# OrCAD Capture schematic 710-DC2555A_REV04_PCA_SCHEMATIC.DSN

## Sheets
1 PAGE2: size Custom; company: ANALOG DEVICES; note: DEMO BOARD BILL OF MATERIALS; note: SINGLE 3.6V, 1A LiFePO4 CELL WIRELESS BATTERY CHARGER
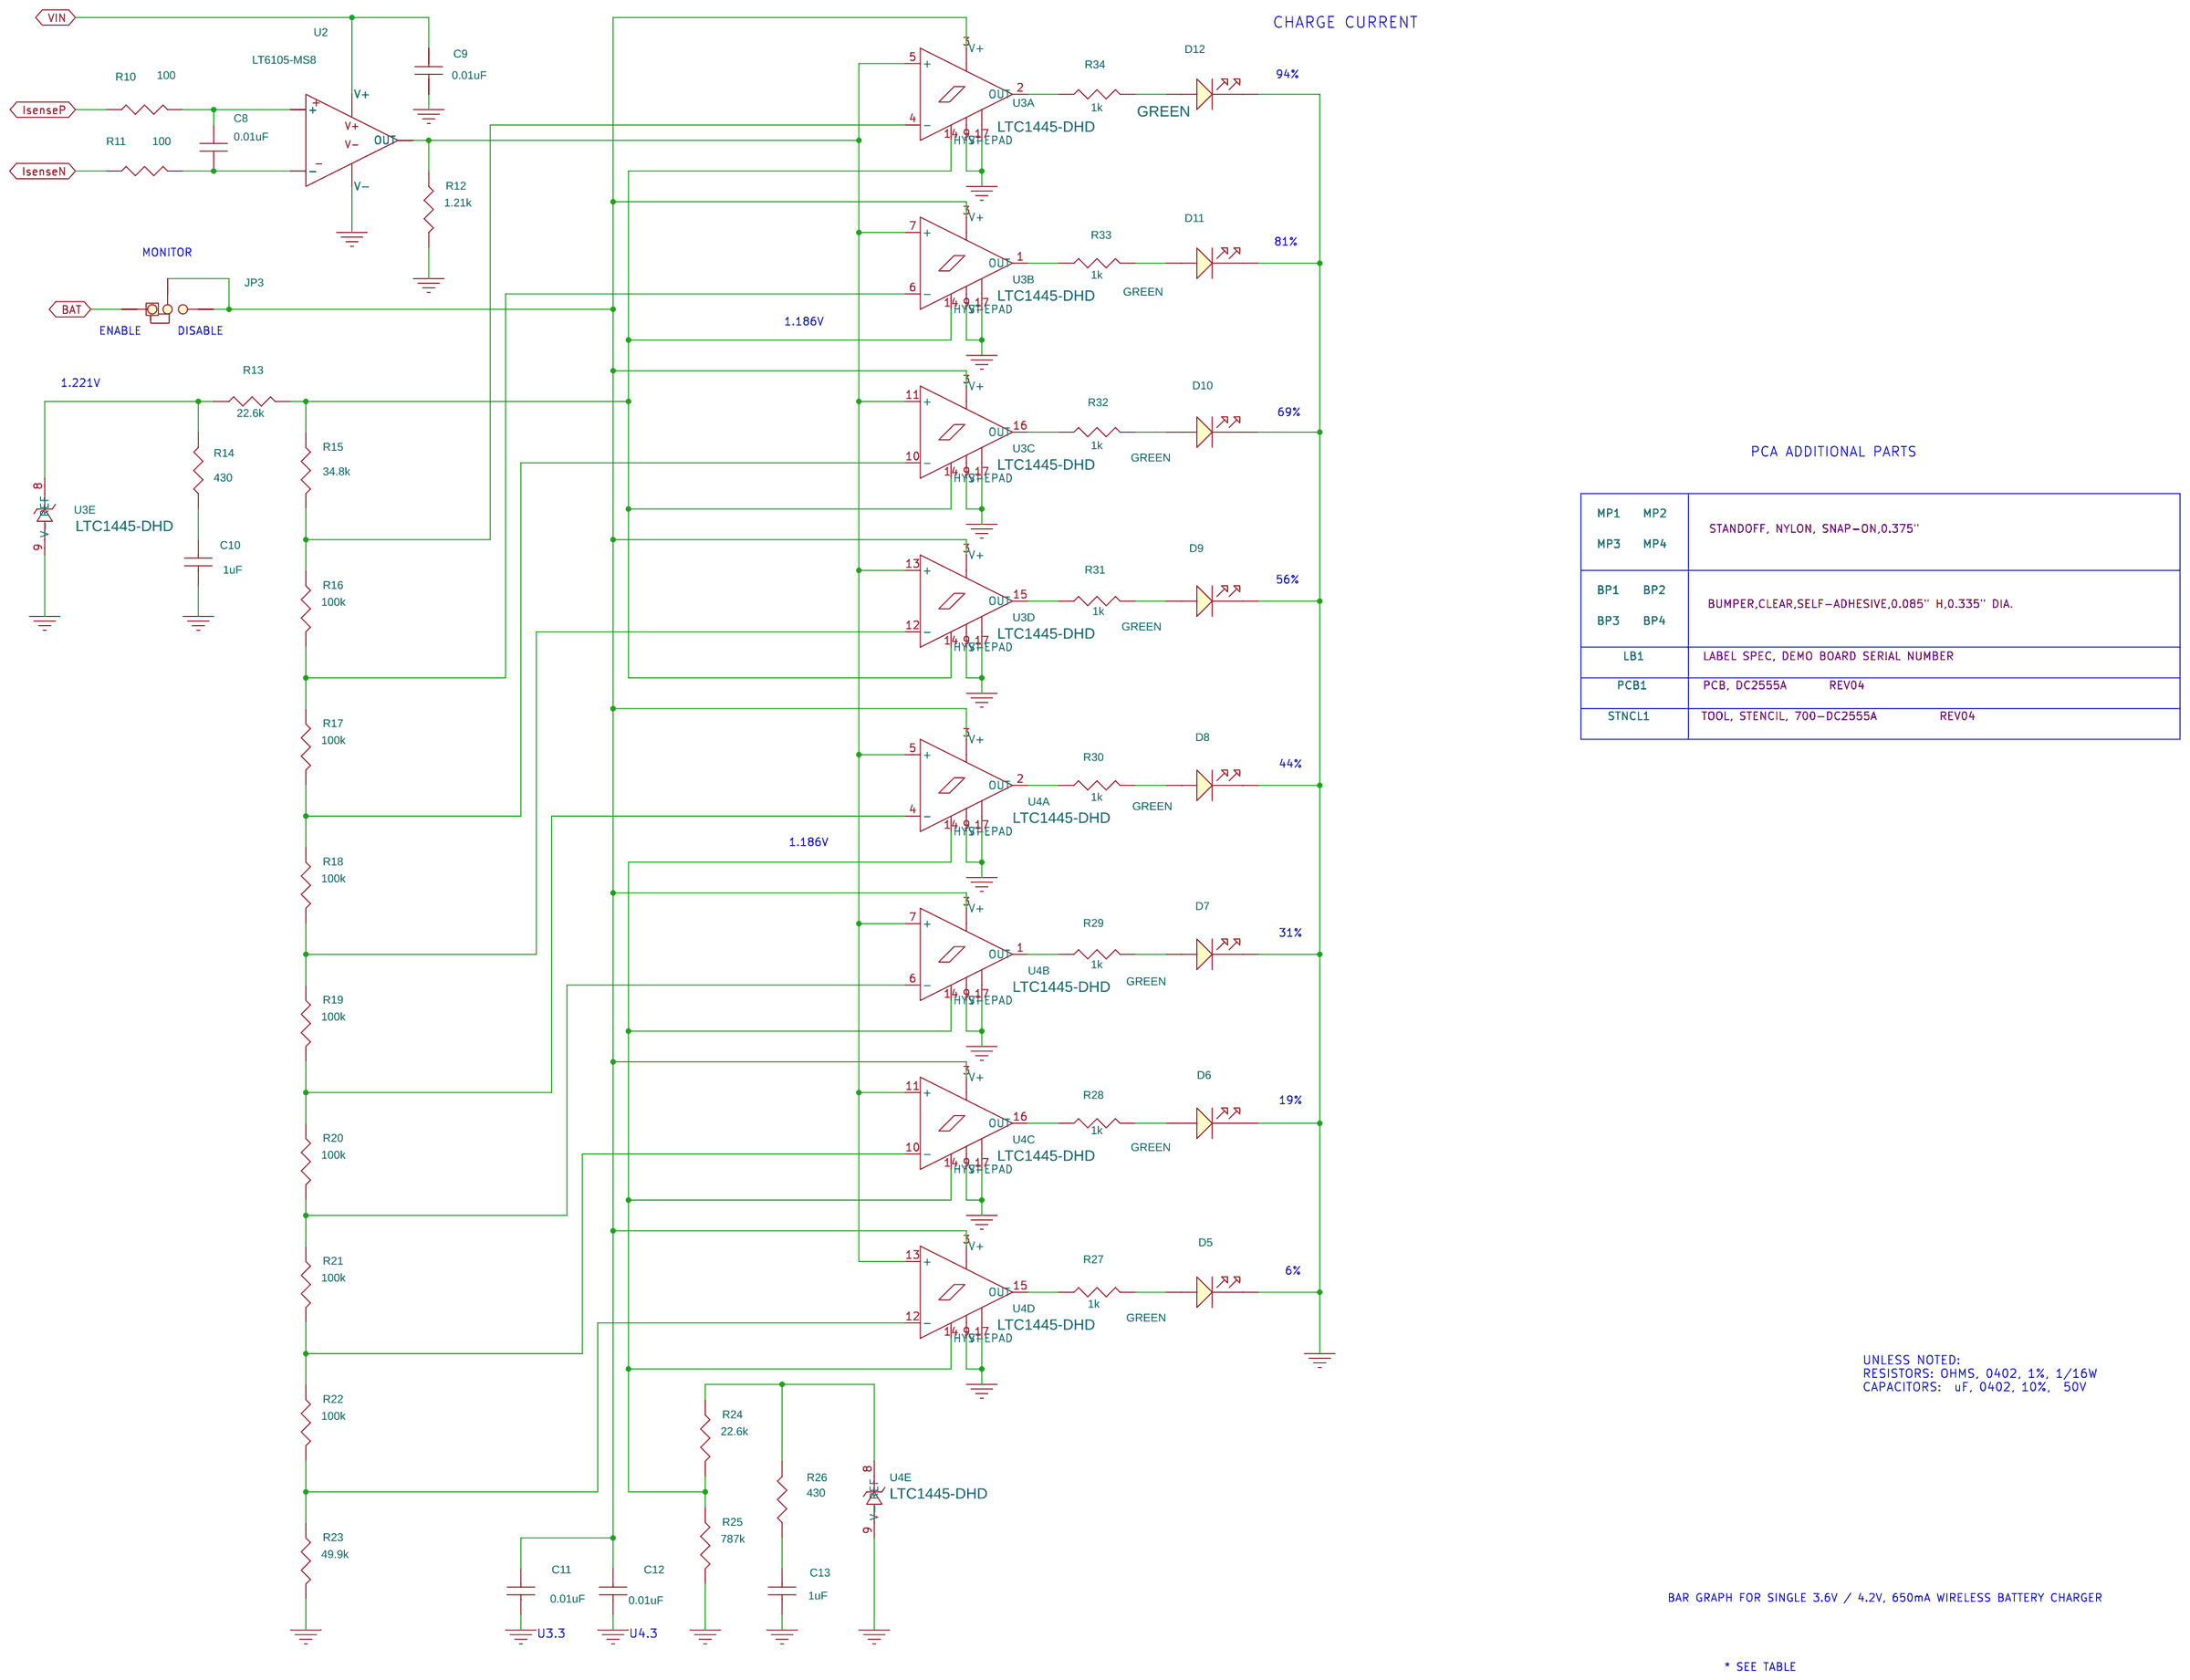
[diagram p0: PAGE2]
2 PAGE1: size Custom
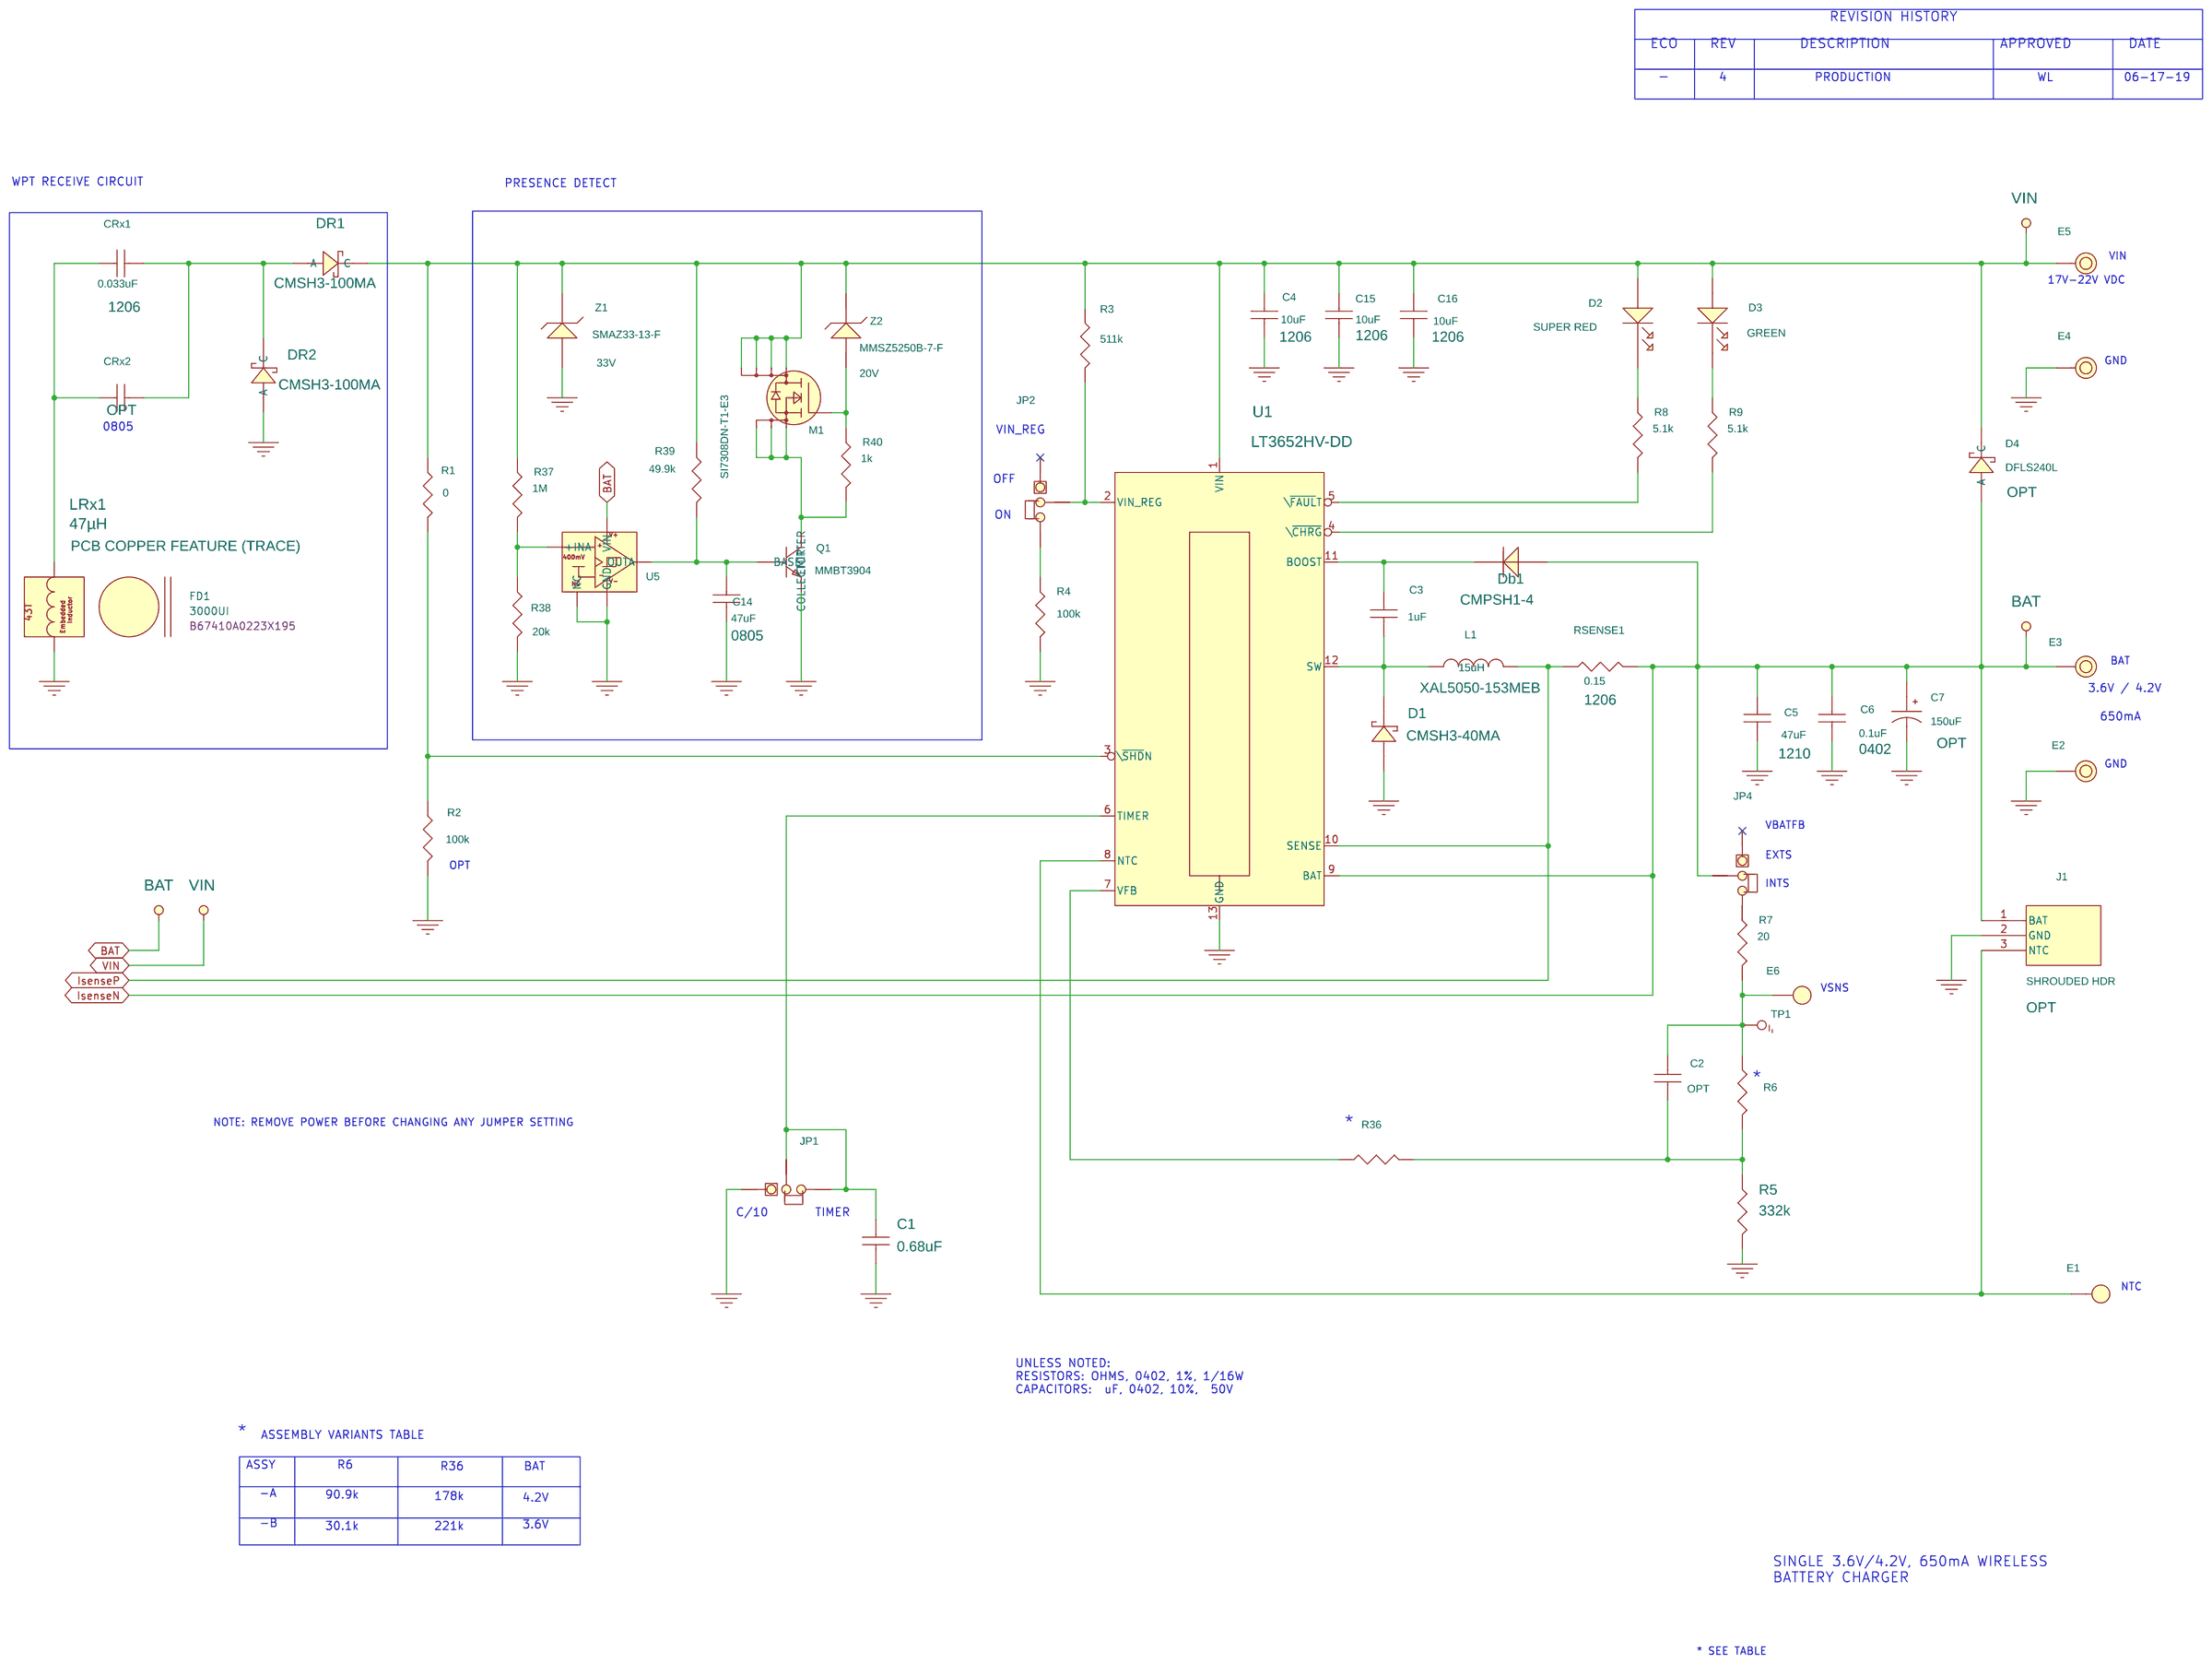
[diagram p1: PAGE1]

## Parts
sheet PAGE1
C1  0.68uF  [CC0402M]
C2  OPT  [CC0402M]
C3  1uF  [CC0402M]
C4  10uF  [CC1206N]
C5  47uF  [CC1210N]
C6  0.1uF  [CC0402M]
C7  150uF  [CAPMP7343N]
C14  47uF  [CC0805N]
C15  10uF  [CC1206N]
C16  10uF  [CC1206N]
CRx1  0.033uF  [CC1206N]
CRx2  1800pF  [CC0805N]
D1  CMSH3-40MA  [SMA-N]
D2  SUPER RED  [LED_0603]
D3  GREEN  [LED_0603]
D4  DFLS240L  [POWERDI-123]
Db1  CMPSH1-4  [SOT23F-3N]
DR1  CMSH3-100MA  [SMA-N]
DR2  CMSH3-100MA  [SMA-N]
E1  TEST POINT  [MILLMAX2308]
E2  TEST POINT  [MILLMAX2501]
E3  TEST POINT  [MILLMAX2501]
E4  TEST POINT  [MILLMAX2501]
E5  TEST POINT  [MILLMAX2501]
E6  TEST POINT  [MILLMAX2308]
FD1  3000UI  [TDK-B67410A223X195]
J1  SHROUDED HDR  [CON-HIROSE-DF3-3P-2DSA]
JP1  HDR.  [HD1X3-079]
JP2  HDR.  [HD1X3-079]
JP4  HDR.  [HD1X3-079]
L1  15uH  [COILCRAFT-XAL50]
LRx1  47µH  [EMB_COIL_43T]
M1  SI7308DN-T1-E3  [VISHAY-POWERPAK1212-8S]
Q1  MMBT3904  [SOT23-3N]
R1  0  [CR0402M]
R2  100k  [CR0402M]
R3  511k  [CR0402M]
R4  100k  [CR0402M]
R5  332k  [CR0402M]
R6  90.9k  [CR0402M]
R7  20  [CR0402M]
R8  5.1k  [CR0603N]
R9  5.1k  [CR0603N]
R36  178k  [CR0402M]
R37  1M  [CR0402M]
R38  20k  [CR0402M]
R39  49.9k  [CR0402M]
R40  1k  [CR0402M]
RSENSE1  0.15  [SUSUMU-KRL1632]
TP1  COPPER FEATURE PAD  [PADSTYLE1]
U1  LT3652HV-DD  [LTC-DD-12-1725]
U5  LT6703HV-S5-3  [LTC-S5-5-1635]
XJP3  SHUNT
XJP4  SHUNT
XJP6  SHUNT
Z1  SMAZ33-13-F  [SMA-N]
Z2  MMSZ5250B-7-F  [SOD-123N]
sheet PAGE2
BP1  BUMPER  [UNASSIGNED]
BP2  BUMPER  [UNASSIGNED]
BP3  BUMPER  [UNASSIGNED]
BP4  BUMPER  [UNASSIGNED]
C8  0.01uF  [CC0402M]
C9  0.01uF  [CC0402M]
C10  1uF  [CC0402M]
C11  0.01uF  [CC0402M]
C12  0.01uF  [CC0402M]
C13  1uF  [CC0402M]
D5  GREEN  [LED_0603]
D6  GREEN  [LED_0603]
D7  GREEN  [LED_0603]
D8  GREEN  [LED_0603]
D9  GREEN  [LED_0603]
D10  GREEN  [LED_0603]
D11  GREEN  [LED_0603]
D12  GREEN  [LED_0603]
JP3  HDR.  [HD1X3-079]
LB1  LABEL  [895-0154_REV01]
MP1  STANDOFF, NYLON, SNAP-ON  [KEYSTONE_8829-8834]
MP2  STANDOFF, NYLON, SNAP-ON  [KEYSTONE_8829-8834]
MP3  STANDOFF, NYLON, SNAP-ON  [KEYSTONE_8829-8834]
MP4  STANDOFF, NYLON, SNAP-ON  [KEYSTONE_8829-8834]
PCB1  PCB, DC2555A
R10  100  [CR0402M]
R11  100  [CR0402M]
R12  1.21k  [CR0402M]
R13  22.6k  [CR0402M]
R14  430  [CR0402M]
R15  34.8k  [CR0402M]
R16  100k  [CR0402M]
R17  100k  [CR0402M]
R18  100k  [CR0402M]
R19  100k  [CR0402M]
R20  100k  [CR0402M]
R21  100k  [CR0402M]
R22  100k  [CR0402M]
R23  49.9k  [CR0402M]
R24  22.6k  [CR0402M]
R25  787k  [CR0402M]
R26  430  [CR0402M]
R27  1k  [CR0402M]
R28  1k  [CR0402M]
R29  1k  [CR0402M]
R30  1k  [CR0402M]
R31  1k  [CR0402M]
R32  1k  [CR0402M]
R33  1k  [CR0402M]
R34  1k  [CR0402M]
STNCL1  TOOL, STENCIL, 700-DC2555A
U2  LT6105-MS8  [LTC-MS8-8-1660]
U3  LTC1445-DHD  [LTC-DHD-16-1707]  (sections A,B,C,D,E)
U4  LTC1445-DHD  [LTC-DHD-16-1707]  (sections A,B,C,D,E)
XJP5  SHUNT

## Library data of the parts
C1 = CAP: CAP.,0.68uF,X5R,10V,10%,0402; CLASS: DISCRETE; Dielectric Type: X5R; FPLIST: CC0402N,CC0402L,CC0402M; Inventory Qty: 12568; Manufacturer: MURATA; Manufacturer PN: GRM155R61A684KE15D; PART_NUMBER: 150-3555; Package Size: 0402; Rated Voltage: 10V; Tolerance: 10%
C2 = CAP: CAP., OPTION, 0402; BOM Notes: NO STUFF; CLASS: DISCRETE; PART_NUMBER: 150-3148; Package Size: 0402; Package Type: SMD
C3 C10 C13 = CAP: CAP.,1uF,X5R,16V,10%,0402; CLASS: DISCRETE; Dielectric Type: X5R; FPLIST: CC0402N,CC0402L,CC0402M; Inventory Qty: 40680; Manufacturer: AVX; Manufacturer PN: 0402YD105KAT2A; PART_NUMBER: 150-0250; Package Size: 0402; Rated Voltage: 16V; Tolerance: 10%
C4 C15 C16 = CAP: CAP.,10uF,X5R,50V,10%,1206; CLASS: DISCRETE; Dielectric Type: X5R; FPLIST: CC1206N,CC1206L,CC1206M; Inventory Qty: 21192; Manufacturer: MURATA; Manufacturer PN: GRM31CR61H106KA12L; PART_NUMBER: 150-0330; Package Size: 1206; Rated Voltage: 50V; Tolerance: 10%
C5 = CAP: CAP.,47uF,X5R,16V,20%,1210; CLASS: DISCRETE; Dielectric Type: X5R; FPLIST: CC1210N,CC1210L,CC1210M; Inventory Qty: 3788; Manufacturer: AVX; Manufacturer PN: 1210YD476MAT2A; PART_NUMBER: 150-3254; Package Size: 1210; Rated Voltage: 16V; Tolerance: 20%
C6 = CAP: CAP.,0.1uF,X5R,50V,10%,0402; CLASS: DISCRETE; Dielectric Type: X5R; FPLIST: CC0402N,CC0402L,CC0402M; Inventory Qty: 1680; Manufacturer: AVX; Manufacturer PN: 04025D104KAT2A; PART_NUMBER: 150-3561; Package Size: 0402; Package Type: Surface Mount, MLCC; Rated Voltage: 50V; Temperature Coefficient: X5R; Tolerance: 10%
C7 = CAP_P_ALT: CAP.,150uF,TANT. POSCAP,10V,20%,7343,D3L; BOM Notes: NO STUFF; CLASS: DISCRETE; Dielectric Type: TANT. POSCAP; FPLIST: CAPMP7343N,CAPMP7343L,CAPMP7343N; Inventory Qty: 0; Manufacturer: PANASONIC; Manufacturer PN: 10TPF150ML; PART_FIELD_01: OPT; PART_NUMBER: 150-2018; Package Size: 7343,D3L; Rated Voltage: 10V; Tolerance: 20%
C14 = CAP: CAP.,47uF,X5R,6.3V,20%,0805; CLASS: DISCRETE; Dielectric Type: X5R; FPLIST: CC0805N,CC0805L,CC0805M; Inventory Qty: 29694; Manufacturer: MURATA; Manufacturer PN: GRM21BR60J476ME15L; PART_NUMBER: 150-0140; Package Size: 0805; Rated Voltage: 6.3V; Tolerance: 20%
CRx1 = CAP: CAP.,0.033uF,NP0,100V,5%,1206; CLASS: DISCRETE; Dielectric Type: NP0; FPLIST: CC1206N,CC1206L,CC1206M; Inventory Qty: 2722; Manufacturer: TDK; Manufacturer PN: C3216NP02A333J160AA; PART_NUMBER: 150-3562; Package Size: 1206; Package Type: Surface Mount, MLCC; Rated Voltage: 100V; Temperature Coefficient: C0G, NP0; Tolerance: 5%
CRx2 = CAP: CAP CER 1800PF 100V C0G 0805; BOM Notes: NO STUFF; CLASS: DISCRETE; Dielectric Type: Capacitors; Manufacturer: TDK Corporation; Manufacturer PN: C2012C0G2A182J085AA; PART_FIELD_01: OPT; PART_NUMBER: TMP-2658; Package Size: 0805 (2012 Metric); Package Type: Surface Mount, MLCC; Rated Voltage: 100V; Temperature Coefficient: C0G, NP0; Tolerance: 5%
D1 = DIODE_SCHOTTKY_A_ALT: DIODE,SCHOTTKY RECT.,40V,3A,SMA; CLASS: DISCRETE; FPLIST: SMA-N,SMA-L,SMA-M; Inventory Qty: 920; Manufacturer: CENTRAL SEMI.; Manufacturer PN: CMSH3-40MA TR13 LEAD FREE; Max Forward Current or Rated Power: 3A; PART_NUMBER: 210-0191; Package Size: DO-214AC, SMA; Package Type: SMA; Rated Voltage: 40V; Rated Voltage or Zener Voltage: 40V
D2 = LED_ALT: LED,SUPER RED,MILKY WHITE DIFF.,0603; CLASS: DISCRETE; Inventory Qty: 8820; Manufacturer: LUMEX; Manufacturer PN: SML-LX0603SRW-TR; PART_NUMBER: 270-0084; Package Size: 0603 (1608 Metric); Package Type: 0603
D3 D5-D12 = LED_ALT: LED,GREEN,MILKY WHITE DIFFUSED,0603; CLASS: DISCRETE; Inventory Qty: 9994; Manufacturer: LUMEX; Manufacturer PN: SML-LX0603SUGW-TR; PART_NUMBER: 270-0091; Package Size: 0603 (1608 Metric); Package Type: 0603
D4 = DIODE_SCHOTTKY_A: DIODE,SCHOTTKY,40V,2A,PowerDI123-2,AEC-Q101; BOM NOTES: NO STUFF; CLASS: DISCRETE; Inventory Qty: 4023; Manufacturer: DIODES INC.; Manufacturer PN: DFLS240L-7; Max Forward Current or Rated Power: 2A; PART_FIELD_01: OPT; PART_NUMBER: 210-0158; Package Type: PowerDI123-2; Rated Voltage: 40V; Rated Voltage or Zener Voltage: 40V
Db1 = DIODE_SOT_1: DIODE,SCHOTTKY RECT.,40V,1.75A,SOT-23F; CLASS: DISCRETE; FPLIST: SOT23-3N,SOT23-3L,SOT23-3M; Inventory Qty: 780; Manufacturer: CENTRAL SEMI.; Manufacturer PN: CMPSH1-4 TR LEAD FREE; Max Forward Current or Rated Power: 1.75A; PART_NUMBER: 210-0193; Package Size: SOT-23-3 Flat Leads; Package Type: SOT-23F; Rated Voltage: 40V; Rated Voltage or Zener Voltage: 40V
DR1 DR2 = DIODE_SCHOTTKY_A: DIODE,SCHOTTKY,100V,3A,SMA; CLASS: DISCRETE; FPLIST: SMA-N,SMA-L,SMA-M; Inventory Qty: 800; Manufacturer: CENTRAL SEMI.; Manufacturer PN: CMSH3-100MA TR13 PBFREE; Max Forward Current or Rated Power: 3A; PART_NUMBER: 210-0275; Package Size: DO-214AC, SMA; Package Type: SMA; Rated Voltage: 100V; Rated Voltage or Zener Voltage: 100V
E1 E6 = TEST_POINT_.156_MILL-MAX_2308: TEST POINT,TURRET,0.064" MTG. HOLE,PCB 0.062" THICK; CLASS: IO; FPLIST: MILLMAX2308,MILLMAX2308-2; Inventory Qty: 804832; Manufacturer: MILL-MAX; Manufacturer PN: 2308-2-00-80-00-00-07-0; PART_NUMBER: 260-0004
E2-E5 = TESTPOINT_.219_MILL-MAX_2501: TEST POINT,TURRET,0.094" MTG. HOLE,PCB 0.062" THICK; CLASS: IO; Inventory Qty: 509910; Manufacturer: MILL-MAX; Manufacturer PN: 2501-2-00-80-00-00-07-0; PART_NUMBER: 260-0003
FD1 = IND-FERRITE_DISK: IND.,3000ui,FERRITE DISK,+/-25%,ROD25.5/0.6; CLASS: DISCRETE; Inventory Qty: 1824; Manufacturer: TDK; Manufacturer PN: B67410A0223X195; PART_NUMBER: 200-0522; Tolerance: +/-25%
J1 = CON-HIROSE-DF3-3P-2DSA: CONN.,SHROUDED HDR,MALE,1x3,2mm,STR, THT,AU; BOM Notes: NO STUFF; CLASS: IO; Inventory Qty: 0; Manufacturer: HIROSE ELECTRIC; Manufacturer PN: DF3-3P-2DSA(01); Operating Temperature Minimum: -55C - 105C; PART_FIELD_01: OPT; PART_NUMBER: 250-0713
JP1-JP4 = 1X3_C: CONN.,HDR.,MALE,1x3,2mm,THT, STR,NO SUBS. ALLOWED; CLASS: IO; Inventory Qty: 9734; Manufacturer: SAMTEC; Manufacturer PN: TMM-103-02-L-S; PART_NUMBER: 250-0638
L1 = IND: IND.,15uH,PWR,20%,3.9A,76.70mOhms,5.48x5.28mm,AEC-Q200; CLASS: DISCRETE; Inventory Qty: 0; Manufacturer: COILCRAFT; Manufacturer PN: XAL5050-153MEB; PART_NUMBER: 200-0514; Package Size: 5.48x5.28mm; Tolerance: 20%
LRx1 = LPS4018-153MLC_1: PART_FIELD_01: PCB COPPER FEATURE (TRACE)
M1 = MOSFET_N-CH_G: XSTR.,MOSFET,N-CH,60V,6A,PowerPAK 1212-8; CLASS: DISCRETE; Inventory Qty: 2624; Manufacturer: VISHAY; Manufacturer PN: Si7308DN-T1-GE3; PART_NUMBER: 240-0291; Package Size: PowerPAK® 1212-8; Package Type: PowerPAK 1212-8; Polarity: N-Channel; Rated Voltage: 60V
Q1 = MMBT3904_SOT-23: XSTR.,NPN,40V,200mA,SOT23-3; CLASS: DISCRETE; FPLIST: SOT23-3N,SOT23-3L,SOT23-3M; Inventory Qty: 14639; Manufacturer: FAIRCHILD SEMI; PART_NUMBER: 240-0014; Package Type: SOT23-3; Rated Voltage: 40V
R1 = RES: RES.,0 OHM,1/16W,0402; CLASS: DISCRETE; FPLIST: CR0402N,CR0402L,CR0402M; Inventory Qty: 222931; Manufacturer: ROHM; Manufacturer PN: MCR01MZPJ000; PART_NUMBER: 100-0215; Package Size: 0402; Rated Power: 1/16W
R2 = RES: RES.,100k OHMS,1%,1/16W,0402,AEC-Q200; CLASS: DISCRETE; FPLIST: CR0402N,CR0402L,CR0402M; Inventory Qty: 136632; Manufacturer: VISHAY; Manufacturer PN: CRCW0402100KFKED; PART_NUMBER: 100-2396; Package Size: 0402; Rated Power: 1/16W; Temperature Coefficient: 100ppm; Tolerance: 1%
R3 = RES: RES.,511k OHMS,1%,1/16W,0402,AEC-Q200; CLASS: DISCRETE; FPLIST: CR0402N,CR0402L,CR0402M; Inventory Qty: 20028; Manufacturer: NIC; Manufacturer PN: NRC04F5113TRF; PART_NUMBER: 100-0583; Package Size: 0402; Rated Power: 1/16W; Temperature Coefficient: +/-100PPM; Tolerance: 1%
R4 = RES: RES.,100k OHMS,1%,1/10W,0402,AEC-Q200; CLASS: DISCRETE; FPLIST: CR0402N,CR0402L,CR0402M; Inventory Qty: 127964; Manufacturer: KOA SPEER; Manufacturer PN: RK73H1ETTP1003F; PART_NUMBER: 100-2407; Package Size: 0402; Rated Power: 1/10W; Temperature Coefficient: 100ppm/C; Tolerance: 1%
R5 = RES: RES.,332k OHMS,1%,1/16W,0402,AEC-Q200; CLASS: DISCRETE; FPLIST: CR0402N,CR0402L,CR0402M; Inventory Qty: 16850; Manufacturer: NIC; Manufacturer PN: NRC04F3323TRF; PART_NUMBER: 100-2664; Package Size: 0402; Rated Power: 1/16W; Temperature Coefficient: 100ppm/C; Tolerance: 1%
R6 = RES: RES.,90.9k OHMS,1%,1/16W,0402,AEC-Q200; CLASS: DISCRETE; FPLIST: CR0402N,CR0402L,CR0402M; Inventory Qty: 69042; Manufacturer: NIC; Manufacturer PN: NRC04F9092TRF; PART_NUMBER: 100-2879; Package Size: 0402; Rated Power: 1/16W; Temperature Coefficient: 100ppm; Tolerance: 1%
R7 = RES: RES.,20 OHMS,5%,1/16W,0402; CLASS: DISCRETE; FPLIST: CR0402N,CR0402L,CR0402M; Inventory Qty: 14501; Manufacturer: KOA SPEER; Manufacturer PN: RK73B1ETTP200J; PART_NUMBER: 100-2384; Package Size: 0402; Rated Power: 1/16W; Temperature Coefficient: 200ppm/C; Tolerance: 5%
R8 R9 = RES: RES.,5.1k OHMS,5%,1/10W,0603,AEC-Q200; CLASS: DISCRETE; FPLIST: CR0603N,CR0603L,CR0603M; Inventory Qty: 35732; Manufacturer: NIC; Manufacturer PN: NRC06J512TRF; PART_NUMBER: 100-0463; Package Size: 0603; Rated Power: 1/10W; Temperature Coefficient: 200ppm; Tolerance: 5%
R36 = RES: RES.,178K OHMS,1%,1/16W,0402,AEC-Q200; CLASS: DISCRETE; FPLIST: CR0402N,CR0402L,CR0402M; Inventory Qty: 5000; Manufacturer: NIC; Manufacturer PN: NRC04F1783TRF; PART_NUMBER: 100-0976; Package Size: 0402; Rated Power: 1/16W; Temperature Coefficient: +/-100PPM; Tolerance: 1%
R37 = RES: RES.,1M OHMS,1%,1/16W,0402,AEC-Q200; CLASS: DISCRETE; FPLIST: CR0402N,CR0402L,CR0402M; Inventory Qty: 93609; Manufacturer: STACKPOLE ELECTRONICS, INC.; Manufacturer PN: RMCF0402FT1M00; PART_NUMBER: 100-2457; Package Size: 0402; Rated Power: 1/16W; Temperature Coefficient: 100ppm; Tolerance: 1%
R38 = RES: RES.,20k OHMS,1%,1/16W,0402,AEC-Q200; CLASS: DISCRETE; FPLIST: CR0402N,CR0402L,CR0402M; Inventory Qty: 11200; Manufacturer: NIC; Manufacturer PN: NRC04F2002TRF; PART_NUMBER: 100-2549; Package Size: 0402; Rated Power: 1/16W; Temperature Coefficient: 100ppm/C; Tolerance: 1%
R23 R39 = RES: RES.,49.9k OHMS,1%,1/16W,0402,AEC-Q200; CLASS: DISCRETE; FPLIST: CR0402N,CR0402L,CR0402M; Inventory Qty: 40010; Manufacturer: NIC; Manufacturer PN: NRC04F4992TRF; PART_NUMBER: 100-2406; Package Size: 0402; Rated Power: 1/16W; Temperature Coefficient: 100ppm/C; Tolerance: 1%
R40 = RES: RES.,1k OHM,1%,1/16W,0402,AEC-Q200; CLASS: DISCRETE; FPLIST: CR0402N,CR0402L,CR0402M; Inventory Qty: 114186; Manufacturer: VISHAY; Manufacturer PN: CRCW04021K00FKED; PART_NUMBER: 100-2456; Package Size: 0402; Rated Power: 1/16W; Temperature Coefficient: 100ppm/C; Tolerance: 1%
RSENSE1 = RES: RES.,0.15 OHM,1%,3/4W,1206,SHORT-SIDE TERM.,AEC-Q200,METAL,SENSE; CLASS: DISCRETE; Inventory Qty: 0; Manufacturer: Susumu; Manufacturer PN: KRL1632E-M-R150-F-T5; PART_NUMBER: 100-1454; Package Size: 1206; Rated Power: 3/4W; Temperature Coefficient: +/-50ppm; Tolerance: 1%
TP1 = PAD_SMALL_FILLED: TESTPOINT, PCB COPPER FEATURE; CLASS: IO; Manufacturer: N/A; Manufacturer PN: N/A; PART_NUMBER: PCBPADS-11
U1 = LT3652HV-DD: IC,PWR Tracking 2A Batt.Charger,3x3 DFN-12; CLASS: IC; Inventory Qty: 0; Manufacturer: LINEAR TECH.; Manufacturer PN: LT3652HVEDD#PBF; PART_NUMBER: LT3652HVEDD#PBF; Package Type: 3x3 DFN-12
U5 = LT6703HV-3-S5: IC,uPower, Comparator w/400mV Ref,SOT23-5; CLASS: IC; Inventory Qty: 0; Manufacturer: LINEAR TECH.; Manufacturer PN: LT6703HVIS5-3#PBF; PART_NUMBER: LT6703HVIS5-3#PBF; Package Size: TSOT-23; Package Type: SOT23-5
XJP3-XJP6 = SHUNT_2MM_B: CONN.,SHUNT,FEMALE,2 POS,2mm; CLASS: IO; Inventory Qty: 63006; Manufacturer: Wurth Elektronik; Manufacturer PN: 60800213421; PART_NUMBER: 250-0485
Z1 = ZENER_ALT: DIODE,ZENER,33V,1W,SMA; CLASS: DISCRETE; Inventory Qty: 0; Manufacturer: DIODES INC.; PART_NUMBER: 210-0443; Package Size: DO-214AC, SMA; Package Type: SMA; Rated Voltage or Zener Voltage: 33V
Z2 = ZENER_ALT: DIODE,ZENER,20V,500mW,SOD-123; CLASS: DISCRETE; Inventory Qty: 0; Manufacturer: DIODES INC.; PART_NUMBER: 210-0444; Package Size: SOD-123; Package Type: SOD-123; Rated Power: 500mW; Rated Voltage or Zener Voltage: 20V
BP1-BP4 = BLANK_MECHANICAL_PART: BUMPER,CLEAR,SELF-ADHESIVE,0.085" H,0.335" DIA.; CLASS: DISCRETE; Inventory Qty: 6096; Manufacturer: KEYSTONE; Manufacturer PN: 784-C; PART_NUMBER: 763-0027
C8 C9 C11 C12 = CAP: CAP.,0.01uF,X7R,50V,10%,0402; CLASS: DISCRETE; Dielectric Type: X7R; FPLIST: CC0402N,CC0402L,CC0402M; Inventory Qty: 65996; Manufacturer: KEMET; Manufacturer PN: C0402C103K5RAC7867; PART_NUMBER: 150-0041; Package Size: 0402; Rated Voltage: 50V; Tolerance: 10%
LB1 = BLANK_LABEL: LABEL SPEC, DEMO BOARD SERIAL NUMBER; Inventory Qty: 0; Manufacturer: BRADY; Manufacturer PN: THT-96-717-10; PART_NUMBER: 895-0154
MP1-MP4 = BLANK_PINLESS_MECHANICAL_PART: STANDOFF, NYLON, SNAP-ON,0.375"; CLASS: DISCRETE; Inventory Qty: 158796; Manufacturer: KEYSTONE; Manufacturer PN: 8832; PART_NUMBER: 763-0008
PCB1 = BLANK_PCB_PART: BOM Notes: REV04; CLASS: DISCRETE; Inventory Qty: 0; Manufacturer: PHASE 3; Manufacturer PN: 600-DC2555A; PART_NUMBER: 600-DC2555A
R10 R11 = RES: RES.,100 OHMS,1%,1/16W,0402,AEC-Q200; CLASS: DISCRETE; FPLIST: CR0402N,CR0402L,CR0402M; Inventory Qty: 91341; Manufacturer: KOA SPEER; Manufacturer PN: RK73H1ETTP1000F; PART_NUMBER: 100-0175; Package Size: 0402; Rated Power: 1/16W; Temperature Coefficient: 100ppm/C; Tolerance: 1%
R12 = RES: RES.,1.21k OHMS,1%,1/16W,0402,AEC-Q200; CLASS: DISCRETE; FPLIST: CR0402N,CR0402L,CR0402M; Inventory Qty: 20000; Manufacturer: KOA SPEER; Manufacturer PN: RK73H1ETTP1211F; PART_NUMBER: 100-0011; Package Size: 0402; Rated Power: 1/16W; Temperature Coefficient: 100ppm/C; Tolerance: 1%
R13 R24 = RES: RES.,22.6k OHMS,1%,1/16W,0402,AEC-Q200; CLASS: DISCRETE; FPLIST: CR0402N,CR0402L,CR0402M; Inventory Qty: 78048; Manufacturer: NIC; Manufacturer PN: NRC04F2262TRF; PART_NUMBER: 100-2975; Package Size: 0402; Rated Power: 1/16W; Temperature Coefficient: 100; Tolerance: 1%
R14 R26 = RES: RES.,430 OHMS,5%,1/16W,0402; CLASS: DISCRETE; FPLIST: CR0402N,CR0402L,CR0402M; Inventory Qty: 39842; Manufacturer: SAMSUNG; Manufacturer PN: RC1005J431CS; PART_NUMBER: 100-0472; Package Size: 0402; Rated Power: 1/16W; Temperature Coefficient: +/-100PPM; Tolerance: 5%
R15 = RES: RES.,34.8k OHMS,1%,1/10W,0402,AEC-Q200; CLASS: DISCRETE; FPLIST: CR0402N,CR0402L,CR0402M; Inventory Qty: 5900; Manufacturer: KOA SPEER; Manufacturer PN: RK73H1ETTP3482F; PART_NUMBER: 100-0734; Package Size: 0402; Rated Power: 1/10W; Temperature Coefficient: 100ppm; Tolerance: 1%
R16-R22 = RES: RES.,100k OHMS,5%,1/16W,0402,AEC-Q200; CLASS: DISCRETE; FPLIST: CR0402N,CR0402L,CR0402M; Inventory Qty: 49572; Manufacturer: NIC; Manufacturer PN: NRC04J104TRF; PART_NUMBER: 100-0359; Package Size: 0402; Rated Power: 1/16W; Temperature Coefficient: 200ppm/C; Tolerance: 5%
R25 = RES: RES.,787k OHMS,1%,1/16W,0402,AEC-Q200; CLASS: DISCRETE; FPLIST: CR0402N,CR0402L,CR0402M; Inventory Qty: 33778; Manufacturer: NIC; Manufacturer PN: NRC04F7873TRF; PART_NUMBER: 100-0326; Package Size: 0402; Rated Power: 1/16W; Temperature Coefficient: 100ppm/C; Tolerance: 1%
R27-R34 = RES: RES.,1k OHM,5%,1/16W,0402,AEC-Q200; CLASS: DISCRETE; FPLIST: CR0402N,CR0402L,CR0402M; Inventory Qty: 83731; Manufacturer: NIC; Manufacturer PN: NRC04J102TRF; PART_NUMBER: 100-2397; Package Size: 0402; Rated Power: 1/16W; Temperature Coefficient: 200ppm; Tolerance: 5%
STNCL1 = BLANK_STENCIL_PART: BOM Notes: REV04; CLASS: DISCRETE; Inventory Qty: 0; Manufacturer: LINEAR TECH.; Manufacturer PN: 830-DC2555A; PART_NUMBER: 830-DC2555A
U2 = LT6105-MS8: IC,CURRENT SENSE AMP,MSOP-8; CLASS: IC; Inventory Qty: 20; Manufacturer: LINEAR TECH.; Manufacturer PN: LT6105CMS8#PBF; PART_NUMBER: LT6105CMS8#PBF; Package Size: 8-TSSOP, 8-MSOP (0.118", 3.00mm Width); Package Type: MSOP-8; Supply Voltage: 2.85 V - 36 V, 1.425 V - 18 V
U3 U4 = LTC1443_44_45-DHD: IC,QUAD COMPARATOR LP 1.221VREF,DFN-16 (5x4); CLASS: IC; Inventory Qty: 36; Manufacturer: LINEAR TECH.; Manufacturer PN: LTC1445CDHD#PBF; PART_NUMBER: LTC1445CDHD#PBF; Package Size: 16-WFDFN Exposed Pad; Package Type: DFN-16 (5x4); Supply Voltage: 2V-11V, 1 V-5.5V

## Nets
GND: C1.2 C4.2 C5.2 C6.2 C7.2 C9.2 C10.2 C11.2 C12.2 C13.2 C14.2 C15.2 C16.2 D1.2(A) D5.1(CATHODE) D6.1(CATHODE) D7.1(CATHODE) D8.1(CATHODE) D9.1(CATHODE) D10.1(CATHODE) D11.1(CATHODE) D12.1(CATHODE) DR2.2(A) E2.1 E4.1 J1.2(GND) JP1.1 LRx1.2 Q1.2(EMITTER) R2.2 R4.2 R5.2 R12.2 R23.2 R25.2 R38.2 U1.13(GND) U2.4(V-) U3.9(V-) U3.17(EPAD) U4.9(V-) U4.17(EPAD) U5.2(GND) U5.5(NC) Z1.2(A)
VIN: C4.1 C9.1 C15.1 C16.1 D2.2(ANODE) D3.2(ANODE) D4.1(C) DR1.1(C) E5.1 M1.5(D) M1.6(Dtab) M1.7(Dtab1) M1.8(Dtab2) R1.1 R3.1 R37.1 R39.1 U1.1(VIN) U2.2(V+) Z1.1(C) Z2.1(C)
BAT: C5.1 C6.1 C7.1 D4.2(A) Db1.1 E3.1 J1.1(BAT) JP3.1 JP4.2 R11.1 RSENSE1.2 U1.9(BAT) U5.4(VIN)
IsenseP: L1.2 R10.1 RSENSE1.1 U1.10(SENSE)
N16829716: C1.1 JP1.2 JP1.3 U1.6(TIMER)
N16838606: D3.1(CATHODE) R9.1
N16838659: D2.1(CATHODE) R8.1
N16850982: C3.2 D1.1(C) L1.1 U1.12(SW)
N16856824: E1.1(A) J1.3(NTC) U1.8(NTC)
N16882466: JP2.2 R3.2 U1.2(VIN_REG)
N16888719: C2.2 E6.1(A) R6.1 R7.2 TP1.1
N16892306: C2.1 R5.1 R6.2 R36.2
N16905248: R36.1 U1.7(VFB)
N16907155: C3.1 Db1.3 U1.11(BOOST)
N16908328: R8.2 U1.5(\~{FAUL}T)
N16908845: R9.2 U1.4(\~{CHRG})
N16910697: M1.1(S) M1.2(Stab) M1.3(Stab1) Q1.3(COLLECTOR) R40.2
N16910770: CRx1.2 CRx2.2 DR1.2(A) DR2.1(C)
N16915821: CRx1.1 CRx2.1 LRx1.1
N16935027: R13.1 R14.2 U3.8(REF)
N16935034: R13.2 R15.1 U3.14(HYST)
N16935145: C11.1 C12.1 JP3.2 JP3.3 U3.3(V+) U4.3(V+)
N16935939: R12.1 U2.5(OUT) U3.5(+) U3.7(+) U3.11(+) U3.13(+) U4.5(+) U4.7(+) U4.11(+) U4.13(+)
N16936864: C8.2 R11.2 U2.1(-)
N16936867: C8.1 R10.2 U2.8(+)
N16981836: C13.1 R26.1
N16983719: D9.2(ANODE) R31.2
N17012090: JP2.3 R4.1
N17050170: R1.2 R2.1 U1.3(\~{SHD}N)
N17067404: R24.2 R25.1 U4.14(HYST)
N17104684: R37.2 R38.1 U5.3(+INA)
N17105039: C14.1 Q1.1(BASE) R39.2 U5.1(OUTA)
N17107129: M1.4(G) R40.1 Z2.2(A)
N17109108: JP4.3 R7.1
N17388523: R15.2 R16.1 U3.4(-)
N17388537: R16.2 R17.1 U3.6(-)
N17388551: R17.2 R18.1 U3.10(-)
N17388565: R18.2 R19.1 U3.12(-)
N17388579: R19.2 R20.1 U4.4(-)
N17388621: R22.2 R23.1 U4.12(-)
N17396884: R34.1 U3.2(OUT)
N17396885: R30.1 U4.2(OUT)
N17396886: R31.1 U3.15(OUT)
N17396887: R33.1 U3.1(OUT)
N17396889: R32.1 U3.16(OUT)
N17396890: R27.1 U4.15(OUT)
N17396891: R29.1 U4.1(OUT)
N17397508: R21.2 R22.1 U4.10(-)
N17397664: R20.2 R21.1 U4.6(-)
N17400203: C10.1 R14.1
N17419772: D12.2(ANODE) R34.2
N17419787: D11.2(ANODE) R33.2
N17419802: D10.2(ANODE) R32.2
N17419832: D8.2(ANODE) R30.2
N17419847: D7.2(ANODE) R29.2
N17419862: D6.2(ANODE) R28.2
N17419877: D5.2(ANODE) R27.2
N17423487: R28.1 U4.16(OUT)
N17431016: R24.1 R26.2 U4.8(REF)

Not connected (* = marked no-connect by the designer): JP2 1*; JP4 1*

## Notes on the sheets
sheet 1
- CHARGE CURRENT
- 94%
- 81%
- MONITOR
- ENABLE
- DISABLE
- 1.186V
- 1.221V
- 69%
- PCA ADDITIONAL PARTS
- 56%
- 44%
- 1.186V
- 31%
- 19%
- 6%
- UNLESS NOTED:
  RESISTORS: OHMS, 0402, 1%, 1/16W
  CAPACITORS:  uF, 0402, 10%,  50V
- BAR GRAPH FOR SINGLE 3.6V / 4.2V, 650mA WIRELESS BATTERY CHARGER
- U3.3
- U4.3
- * SEE TABLE
sheet 2
- REVISION HISTORY
- ECO
- REV
- DESCRIPTION
- APPROVED
- DATE
- -
- 4
- PRODUCTION
- WL
- 06-17-19
- WPT RECEIVE CIRCUIT
- PRESENCE DETECT
- VIN
- 17V-22V VDC
- GND
- 0805
- VIN_REG
- OFF
- ON
- BAT
- 3.6V / 4.2V
- 650mA
- GND
- VBATFB
- OPT
- EXTS
- INTS
- VSNS
- *
- NOTE: REMOVE POWER BEFORE CHANGING ANY JUMPER SETTING
- *
- C/10
- TIMER
- NTC
- UNLESS NOTED:
  RESISTORS: OHMS, 0402, 1%, 1/16W
  CAPACITORS:  uF, 0402, 10%,  50V
- *
- ASSEMBLY VARIANTS TABLE
- ASSY
- R6
- R36
- BAT
- -A
- 90.9k
- 178k
- 4.2V
- -B
- 30.1k
- 221k
- 3.6V
- SINGLE 3.6V/4.2V, 650mA WIRELESS
  BATTERY CHARGER
- * SEE TABLE
